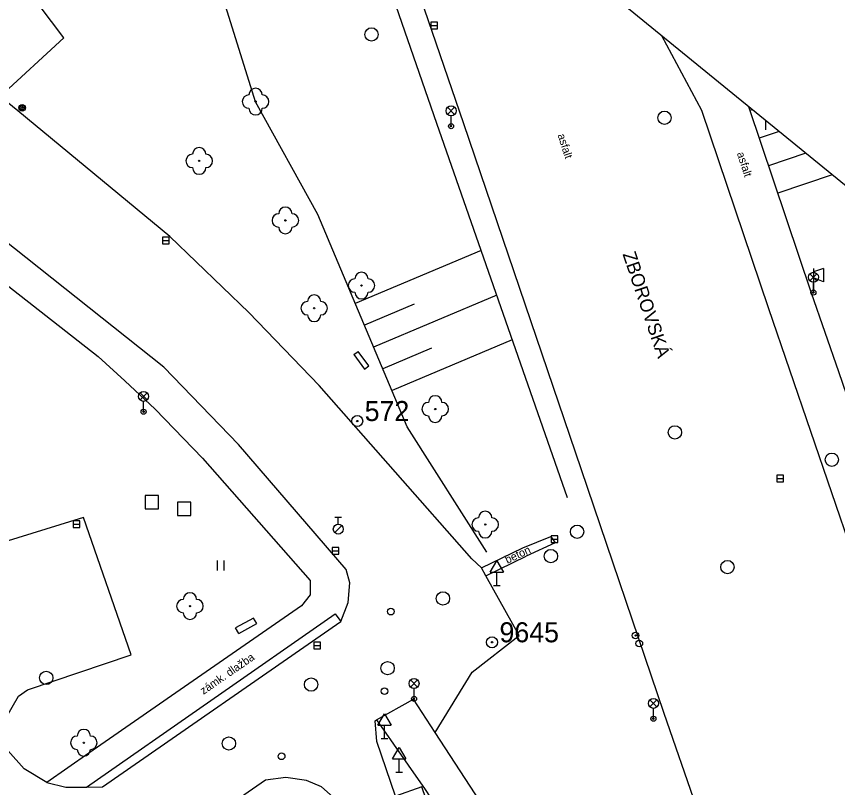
# Model space of a CAD drawing. Extents: x -492431 to -49218, y -1127123 to -112687.
# Drawn here: x -492243 to -492181.4, y -1126982.4 to -1126924.6 of the extents above; entities that cross this region are included whole.
import ezdxf

# ---------------------------------------------------------------- set-up
doc = ezdxf.new("R2010")
doc.units = 0
for name, color, linetype in [('Vrstva 1', 7, 'Continuous'), ('Vrstva 10', 7, 'Continuous'), ('Vrstva 11', 7, 'Continuous'), ('Vrstva 14', 7, 'Continuous'), ('Vrstva 15', 7, 'Continuous'), ('Vrstva 22', 7, 'Continuous'), ('Vrstva 24', 7, 'Continuous'), ('Vrstva 25', 7, 'Continuous'), ('Vrstva 26', 7, 'Continuous'), ('Vrstva 27', 7, 'Continuous'), ('Vrstva 28', 7, 'Continuous'), ('Vrstva 31', 7, 'Continuous'), ('Vrstva 33', 7, 'Continuous'), ('Vrstva 34', 7, 'Continuous'), ('Vrstva 36', 7, 'Continuous'), ('Vrstva 40', 7, 'Continuous'), ('Vrstva 45', 7, 'Continuous'), ('Vrstva 60', 7, 'Continuous'), ('Vrstva 63', 7, 'Continuous')]:
    doc.layers.add(name, color=color, linetype=linetype)

msp = doc.modelspace()

# ---------------------------------------------------------------- linework, layer by layer
at = {"layer": 'Vrstva 1'}
msp.add_lwpolyline([(-492341.24, -1127122.91), (-492133.025, -1126976.26), (-492272.695, -1126862.455), (-492313.78, -1126867.2)], dxfattribs=at)
at = {"layer": 'Vrstva 10'}
for p, q in [((-492209.47, -1126932.67), (-492218.347, -1126906.738)), ((-492188.124, -1126931.365), (-492183.41, -1126945.33)), ((-492200.68, -1126958.54), (-492209.47, -1126932.67)), ((-492194.44, -1126976.89), (-492200.68, -1126958.54)), ((-492237.76, -1126982.41), (-492219.12, -1126969.41)), ((-492219.12, -1126969.41), (-492218.68, -1126969.98)), ((-492191.78, -1126984.59), (-492194.44, -1126976.89)), ((-492215.99, -1126978.97), (-492216.12, -1126977.42))]:
    msp.add_line(p, q, dxfattribs=at)
for points in [[(-492236.56, -1126982.38), (-492218.68, -1126969.98), (-492218.15, -1126968.55), (-492218.01, -1126967.07), (-492218.28, -1126966.07), (-492226.37, -1126956.7), (-492231.96, -1126950.91), (-492273.13, -1126918.19)], [(-492272.49, -1126922.14), (-492263.24, -1126929.48), (-492236.88, -1126950.1), (-492234.89, -1126951.93), (-492232.6, -1126954.06), (-492229.07, -1126957.73), (-492220.98, -1126966.9), (-492221, -1126967.98), (-492221.64, -1126968.8), (-492231.06, -1126975.34), (-492237.59, -1126979.85), (-492240.73, -1126982.05)], [(-492194.655, -1126926.043), (-492191.64, -1126931.65), (-492186.62, -1126946.51), (-492180.32, -1126964.92), (-492178.25, -1126975.18), (-492178.07, -1126975.94)], [(-492208.13, -1126965.97), (-492208.86, -1126965.28), (-492220.32, -1126952.29), (-492225.58, -1126946.81), (-492231.5, -1126941.12), (-492242.91, -1126931.7), (-492244.26, -1126930.62)], [(-492183.41, -1126945.33), (-492181.38, -1126951.23), (-492179.27, -1126957.36), (-492177.29, -1126963.12)], [(-492240.73, -1126982.05), (-492242.43, -1126981.04), (-492243.65, -1126979.65), (-492243.98, -1126978.13), (-492243.82, -1126977.24), (-492242.86, -1126975.57), (-492242.18, -1126975.1), (-492234.4, -1126972.49), (-492237.99, -1126962.18), (-492254.22, -1126967.21)], [(-492205.03, -1126964.47), (-492202.94, -1126963.62), (-492202.61, -1126964.08), (-492204.79, -1126965.08)], [(-492208.13, -1126965.97), (-492205.03, -1126964.47)], [(-492207.81, -1126966.55), (-492204.79, -1126965.08)], [(-492207.81, -1126966.55), (-492208.13, -1126965.97)], [(-492211.62, -1126978.31), (-492208.83, -1126973.78), (-492205.32, -1126971.04), (-492207.81, -1126966.55)], [(-492216.12, -1126977.42), (-492216.02, -1126977.36), (-492213.25, -1126975.81)], [(-492211.62, -1126978.31), (-492213.25, -1126975.81)], [(-492216.02, -1126977.36), (-492212.37, -1126982.59), (-492201.01, -1127000)], [(-492187.785, -1127014.829), (-492211.62, -1126978.31)], [(-492212.42, -1126989.23), (-492214.59, -1126983.07), (-492215.99, -1126978.97)], [(-492240.73, -1126982.05), (-492239.31, -1126982.41), (-492237.76, -1126982.41), (-492236.56, -1126982.38)], [(-492217.72, -1126993.8), (-492216.55, -1126993.16), (-492215.95, -1126992.19), (-492215.75, -1126991.26), (-492215.89, -1126990.23), (-492217.62, -1126985.3), (-492218.41, -1126983.91), (-492220.15, -1126982.37), (-492221.26, -1126981.9), (-492222.81, -1126981.68), (-492224.34, -1126981.89), (-492236.07, -1126990)], [(-492212.42, -1126989.23), (-492209.91, -1126988.35), (-492210.97, -1126985.56), (-492211.46, -1126985.73), (-492212.62, -1126982.37), (-492214.59, -1126983.07)]]:
    msp.add_lwpolyline(points, dxfattribs=at)
at = {"layer": 'Vrstva 11'}
msp.add_lwpolyline([(-492244.26, -1126930.62), (-492239.45, -1126926.21), (-492244.15, -1126919.96), (-492246.72, -1126914.84), (-492258.01, -1126903.55)], dxfattribs=at)
at = {"layer": 'Vrstva 14'}
for p, q in [((-492220.41, -1126939.47), (-492225.08, -1126931.01)), ((-492213.71, -1126955.38), (-492220.41, -1126939.47)), ((-492207.75, -1126964.79), (-492213.71, -1126955.38))]:
    msp.add_line(p, q, dxfattribs=at)
for points in [[(-492201.69, -1126960.71), (-492211.5, -1126932.64), (-492221.29, -1126904.35), (-492221.294, -1126904.337)], [(-492225.08, -1126931.01), (-492231.19, -1126911.47), (-492231.36, -1126910.92)]]:
    msp.add_lwpolyline(points, dxfattribs=at)
at = {"layer": 'Vrstva 15'}
for p, q in [((-492187.829, -1126931.605), (-492188.02, -1126931.67)), ((-492185.828, -1126933.236), (-492187.32, -1126933.74)), ((-492183.832, -1126934.862), (-492186.63, -1126935.81)), ((-492181.834, -1126936.489), (-492185.93, -1126937.87)), ((-492208.17, -1126942.15), (-492217.61, -1126946.13)), ((-492207, -1126945.51), (-492216.23, -1126949.4)), ((-492213.18, -1126946.19), (-492216.92, -1126947.76)), ((-492205.83, -1126948.86), (-492214.85, -1126952.66)), ((-492211.89, -1126949.49), (-492215.54, -1126951.03))]:
    msp.add_line(p, q, dxfattribs=at)
at = {"layer": 'Vrstva 22'}
for centre in [(-492225.08, -1126931), (-492229.31, -1126935.45), (-492222.85, -1126939.91), (-492217.14, -1126944.79), (-492220.69, -1126946.49), (-492211.61, -1126954.05), (-492207.86, -1126962.71), (-492230, -1126968.83), (-492237.96, -1126979.07)]:
    msp.add_circle(centre, 0.05, dxfattribs=at)
for centre, start, end in [((-492225.58, -1126931), 90, 270), ((-492225.08, -1126930.5), 360, 180), ((-492224.58, -1126931), 270, 90), ((-492225.08, -1126931.5), 180, 0), ((-492229.31, -1126934.95), 360, 180), ((-492229.81, -1126935.45), 90, 270), ((-492228.81, -1126935.45), 270, 90), ((-492229.31, -1126935.95), 180, 0), ((-492222.85, -1126939.41), 360, 180), ((-492223.35, -1126939.91), 90, 270), ((-492222.35, -1126939.91), 270, 90), ((-492222.85, -1126940.41), 180, 0), ((-492217.14, -1126944.29), 360, 180), ((-492217.64, -1126944.79), 90, 270), ((-492216.64, -1126944.79), 270, 90), ((-492217.14, -1126945.29), 180, 0), ((-492220.69, -1126945.99), 360, 180), ((-492221.19, -1126946.49), 90, 270), ((-492220.19, -1126946.49), 270, 90), ((-492220.69, -1126946.99), 180, 0), ((-492211.61, -1126953.55), 360, 180), ((-492212.11, -1126954.05), 90, 270), ((-492211.11, -1126954.05), 270, 90), ((-492211.61, -1126954.55), 180, 0), ((-492207.86, -1126962.21), 360, 180), ((-492208.36, -1126962.71), 90, 270), ((-492207.36, -1126962.71), 270, 90), ((-492207.86, -1126963.21), 180, 0), ((-492230, -1126968.33), 360, 180), ((-492230.5, -1126968.83), 90, 270), ((-492229.5, -1126968.83), 270, 90), ((-492230, -1126969.33), 180, 0), ((-492237.96, -1126978.57), 360, 180), ((-492238.46, -1126979.07), 90, 270), ((-492237.46, -1126979.07), 270, 90), ((-492237.96, -1126979.57), 180, 0)]:
    msp.add_arc(centre, 0.5, start, end, dxfattribs=at)
at = {"layer": 'Vrstva 24'}
for p, q in [((-492217.71, -1126949.96), (-492217.39, -1126949.73)), ((-492217.71, -1126949.96), (-492216.92, -1126951.05)), ((-492226.35, -1126970.88), (-492226.58, -1126970.46)), ((-492226.35, -1126970.88), (-492224.99, -1126970.14))]:
    msp.add_line(p, q, dxfattribs=at)
for points in [[(-492216.92, -1126951.05), (-492216.6, -1126950.82), (-492217.39, -1126949.73)], [(-492224.99, -1126970.14), (-492225.23, -1126969.73), (-492226.58, -1126970.46)]]:
    msp.add_lwpolyline(points, dxfattribs=at)
at = {"layer": 'Vrstva 25'}
for centre, radius in [((-492242.58, -1126931.46), 0.25), ((-492242.58, -1126931.46), 0.158), ((-492242.58, -1126931.46), 0.05), ((-492196.59, -1126971.03), 0.25), ((-492196.59, -1126971.03), 0.05)]:
    msp.add_circle(centre, radius, dxfattribs=at)
at = {"layer": 'Vrstva 26'}
for points in [[(-492233.37, -1126961.53), (-492232.37, -1126961.53), (-492232.37, -1126960.53), (-492233.37, -1126960.53)], [(-492230.93, -1126962.03), (-492229.93, -1126962.03), (-492229.93, -1126961.03), (-492230.93, -1126961.03)]]:
    msp.add_lwpolyline(points, close=True, dxfattribs=at)
at = {"layer": 'Vrstva 27'}
for p, q in [((-492211.94, -1126925.29), (-492211.44, -1126925.29)), ((-492232.07, -1126941.4), (-492231.57, -1126941.4)), ((-492185.99, -1126959.27), (-492185.49, -1126959.27)), ((-492238.76, -1126962.68), (-492238.26, -1126962.68)), ((-492202.92, -1126963.8), (-492202.42, -1126963.8)), ((-492219.35, -1126964.69), (-492218.85, -1126964.69)), ((-492220.71, -1126971.77), (-492220.21, -1126971.77))]:
    msp.add_line(p, q, dxfattribs=at)
for points in [[(-492211.94, -1126925.54), (-492211.44, -1126925.54), (-492211.44, -1126925.04), (-492211.94, -1126925.04)], [(-492232.07, -1126941.65), (-492231.57, -1126941.65), (-492231.57, -1126941.15), (-492232.07, -1126941.15)], [(-492185.99, -1126959.52), (-492185.49, -1126959.52), (-492185.49, -1126959.02), (-492185.99, -1126959.02)], [(-492238.76, -1126962.93), (-492238.26, -1126962.93), (-492238.26, -1126962.43), (-492238.76, -1126962.43)], [(-492202.92, -1126964.05), (-492202.42, -1126964.05), (-492202.42, -1126963.55), (-492202.92, -1126963.55)], [(-492219.35, -1126964.94), (-492218.85, -1126964.94), (-492218.85, -1126964.44), (-492219.35, -1126964.44)], [(-492220.71, -1126972.02), (-492220.21, -1126972.02), (-492220.21, -1126971.52), (-492220.71, -1126971.52)]]:
    msp.add_lwpolyline(points, close=True, dxfattribs=at)
for centre in [(-492216.39, -1126925.96), (-492194.42, -1126932.21), (-492193.64, -1126955.8), (-492181.87, -1126957.85), (-492200.97, -1126963.25), (-492202.94, -1126965.08), (-492189.7, -1126965.9), (-492211.03, -1126968.25), (-492215.18, -1126973.48), (-492240.78, -1126974.21), (-492220.92, -1126974.71), (-492227.08, -1126979.13)]:
    msp.add_circle(centre, 0.5, dxfattribs=at)
at = {"layer": 'Vrstva 28'}
for p, q in [((-492219.13, -1126962.15), (-492218.63, -1126962.15)), ((-492218.88, -1126962.675), (-492218.88, -1126962.15)), ((-492219.145, -1126963.315), (-492218.615, -1126962.785))]:
    msp.add_line(p, q, dxfattribs=at)
for centre, radius in [((-492218.88, -1126963.05), 0.375), ((-492214.94, -1126969.24), 0.25)]:
    msp.add_circle(centre, radius, dxfattribs=at)
at = {"layer": 'Vrstva 31'}
for centre in [(-492196.31, -1126971.63), (-492215.42, -1126975.21), (-492223.13, -1126980.09)]:
    msp.add_circle(centre, 0.25, dxfattribs=at)
at = {"layer": 'Vrstva 33'}
for p, q in [((-492210.685, -1126931.425), (-492210.155, -1126931.955)), ((-492210.685, -1126931.955), (-492210.155, -1126931.425)), ((-492210.42, -1126932.84), (-492210.42, -1126932.065)), ((-492183.515, -1126943.905), (-492182.985, -1126944.435)), ((-492183.515, -1126944.435), (-492182.985, -1126943.905)), ((-492183.25, -1126943.52), (-492183.25, -1126945.27)), ((-492182.5, -1126943.52), (-492183.25, -1126943.77)), ((-492182.5, -1126943.52), (-492182.5, -1126944.52)), ((-492182.5, -1126944.52), (-492183.25, -1126944.22)), ((-492183.25, -1126945.32), (-492183.25, -1126944.545)), ((-492233.745, -1126952.835), (-492233.215, -1126953.365)), ((-492233.745, -1126953.365), (-492233.215, -1126952.835)), ((-492233.48, -1126954.25), (-492233.48, -1126953.475)), ((-492213.465, -1126974.365), (-492212.935, -1126974.895)), ((-492213.465, -1126974.895), (-492212.935, -1126974.365)), ((-492213.2, -1126975.78), (-492213.2, -1126975.005)), ((-492195.515, -1126975.855), (-492194.985, -1126976.385)), ((-492195.515, -1126976.385), (-492194.985, -1126975.855)), ((-492195.25, -1126977.27), (-492195.25, -1126976.495))]:
    msp.add_line(p, q, dxfattribs=at)
for centre, radius in [((-492210.42, -1126931.69), 0.375), ((-492210.42, -1126932.84), 0.19), ((-492210.42, -1126932.84), 0.05), ((-492183.25, -1126944.17), 0.375), ((-492183.25, -1126945.32), 0.19), ((-492183.25, -1126945.32), 0.05), ((-492233.48, -1126953.1), 0.375), ((-492233.48, -1126954.25), 0.19), ((-492233.48, -1126954.25), 0.05), ((-492213.2, -1126974.63), 0.375), ((-492213.2, -1126975.78), 0.19), ((-492213.2, -1126975.78), 0.05), ((-492195.25, -1126976.12), 0.375), ((-492195.25, -1126977.27), 0.19), ((-492195.25, -1126977.27), 0.05)]:
    msp.add_circle(centre, radius, dxfattribs=at)
at = {"layer": 'Vrstva 34'}
for p, q in [((-492186.81, -1126933.11), (-492186.81, -1126932.435)), ((-492207.49, -1126966.29), (-492206.99, -1126965.44)), ((-492206.99, -1126965.44), (-492206.49, -1126966.29)), ((-492207.49, -1126966.29), (-492206.49, -1126966.29)), ((-492206.99, -1126967.29), (-492206.99, -1126966.29)), ((-492207.24, -1126967.29), (-492206.74, -1126967.29)), ((-492215.91, -1126977.75), (-492215.41, -1126976.9)), ((-492215.41, -1126976.9), (-492214.91, -1126977.75)), ((-492215.91, -1126977.75), (-492214.91, -1126977.75)), ((-492215.41, -1126978.75), (-492215.41, -1126977.75)), ((-492215.66, -1126978.75), (-492215.16, -1126978.75)), ((-492214.82, -1126980.27), (-492214.32, -1126979.42)), ((-492214.32, -1126979.42), (-492213.82, -1126980.27)), ((-492214.82, -1126980.27), (-492213.82, -1126980.27)), ((-492214.32, -1126981.27), (-492214.32, -1126980.27)), ((-492214.57, -1126981.27), (-492214.07, -1126981.27))]:
    msp.add_line(p, q, dxfattribs=at)
at = {"layer": 'Vrstva 36'}
for p, q in [((-492227.93, -1126966.16), (-492227.93, -1126965.41)), ((-492227.43, -1126966.16), (-492227.43, -1126965.41))]:
    msp.add_line(p, q, dxfattribs=at)
at = {"layer": 'Vrstva 60'}
msp.add_lwpolyline([(-492166.731, -1127000), (-492133.025, -1126976.26), (-492272.695, -1126862.455), (-492313.78, -1126867.2), (-492431.031, -1126895.427), (-492431.031, -1127000)], dxfattribs=at)
at = {"layer": 'Vrstva 63'}
for centre, radius in [((-492217.46, -1126954.95), 0.412), ((-492217.46, -1126954.95), 0.05), ((-492207.35, -1126971.54), 0.412), ((-492207.35, -1126971.54), 0.05)]:
    msp.add_circle(centre, radius, dxfattribs=at)

# ---------------------------------------------------------------- texts
at = {"layer": 'Vrstva 40'}
for s, rotation, p in [('asfalt', 287.9881, (-492202.448, -1126933.506)), ('asfalt', 287.9881, (-492188.998, -1126934.876)), ('beton', 25.00389, (-492206.209, -1126965.659)), ('zámk. dlažba', 34.74178, (-492228.985, -1126975.485))]:
    msp.add_text(s, height=0.6, rotation=rotation, dxfattribs=at).set_placement(p)
at = {"layer": 'Vrstva 45'}
msp.add_text('ZBOROVSKÁ', height=1, rotation=288.67726, dxfattribs=at).set_placement((-492197.573, -1126942.432))
at = {"layer": 'Vrstva 63'}
for s, p in [(' 572', (-492217.46, -1126954.95)), (' 9645', (-492207.35, -1126971.54))]:
    msp.add_text(s, height=1.5, dxfattribs=at).set_placement(p)

doc.saveas('drawing.dxf')
